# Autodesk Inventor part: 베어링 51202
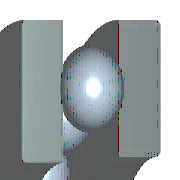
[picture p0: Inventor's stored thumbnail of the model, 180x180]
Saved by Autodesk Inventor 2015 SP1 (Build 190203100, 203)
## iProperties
Created: 2012-02
Part Number: 베어링 51202
Material: 강철, 연강
Description: 롤링 베어링 - 플랫 뒷면이 있는 스러스트 볼 베어링
Document SubType Name: Modeling
Standard: KS B 2022
Designer: mduedu
Standards Organization: KS
Language: ko-KR
Size Designation: 51202 - 15 x 32 x 12
Categories: <MemberInstance><Categories><Category DisplayName="샤프트 부품" InternalName="7f7aeb1f-a693-4053-b835-cee3144e0d98" Mnemonic="SHFT"><Category DisplayName="베어링" Inter
Density: 1 g/cm^3
Appearance: 진녹색
IsCustomPart: 1
Author: mduedu
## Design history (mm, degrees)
sketch "스케치1" dims "d3" = 5.28 (= 0.44 x KB)
  geometry: L1 (6, 9.61)-(6, 14.89); L2 (8.64, 12.25)-(3.36, 12.25); L3 (3.6, 16)-(0, 16); L4 (3.6, 7.5)-(0, 7.5); L5 (8.4, 13.35)-(8.4, 16); L6 (8.4, 16)-(12, 16); L7 (12, 16)-(12, 8.5); L8 (12, 8.5)-(8.4, 8.5); L9 (8.4, 8.5)-(8.4, 11.15); L10 (3.6, 16)-(3.6, 13.35); L11 (3.6, 11.15)-(3.6, 7.5); L12 (-1.8, 0)-(10.8, 0) reference; L13 (0, -0.022)-(0, 5.522) reference; 1 further point
  constraints: 22 end point, 5 perpendicular, 2 equal length, 2 midpoint, 2 parallel, 2 point on line, 1 collinear, 10 other
  dimensions: "d8" = 4.8 diameter of L11 L1 (= 0.4 x KB); "d11" = 15 diameter of L4 L12 (= WD); "d12" = 17 diameter of L8 L12 (= KAD1); "d13" = 32 diameter of L3 L12 (= KID1); "d14" = 32 diameter of L6 L12 (= BD); "d15" = 24.5 diameter of point (6, 12.25) L12 (= 0.5 x KID1 + 0.5 x KAD1); "d16" = 6 distance from line of point (6, 12.25) L13 (= 0.5 x KB); "d18" = 12 distance between parallel lines of L7 L13 (= KB)
revolve "본체" stored, may be unused: angle "d9" = 90 deg
revolve "볼" stored, may be unused: angle "d10" = 90 deg
pattern_circular "IDS_ARRAYBALL[SIMPL:T]" dims angle "d2" = 360 deg
body "Solid1"
fillet "모깎기1" dims "d4" = 0.6 (= KRS)
fillet "모깎기2" dims "d5" = 0.6 (= KRS)
other parameters: "WD" = 15 [user parameter; used in 2 equation terms], "KAD1" = 17 [user parameter; used in 3 equation terms], "KID1" = 32 [user parameter; used in 3 equation terms], "BD" = 32 [user parameter; used in 2 equation terms], "KB" = 12 [user parameter; used in 6 equation terms], "KRS" = 0.6 [user parameter; used in 2 equation terms], "d0" = 2.4 (= 0.2 x KB), "d6" = 0, "d7" = 0, "d19" = 0, "d41" = 0, "d42" = 0, "WR" = 7.5 (= 0.5 x WD) [user parameter], "BC" = 1.65e+07 [user parameter], "BBA" = 90 deg [user parameter], "BC0" = 2.7e+07 [user parameter], "BR" = 16 (= 0.5 x BD) [user parameter]
